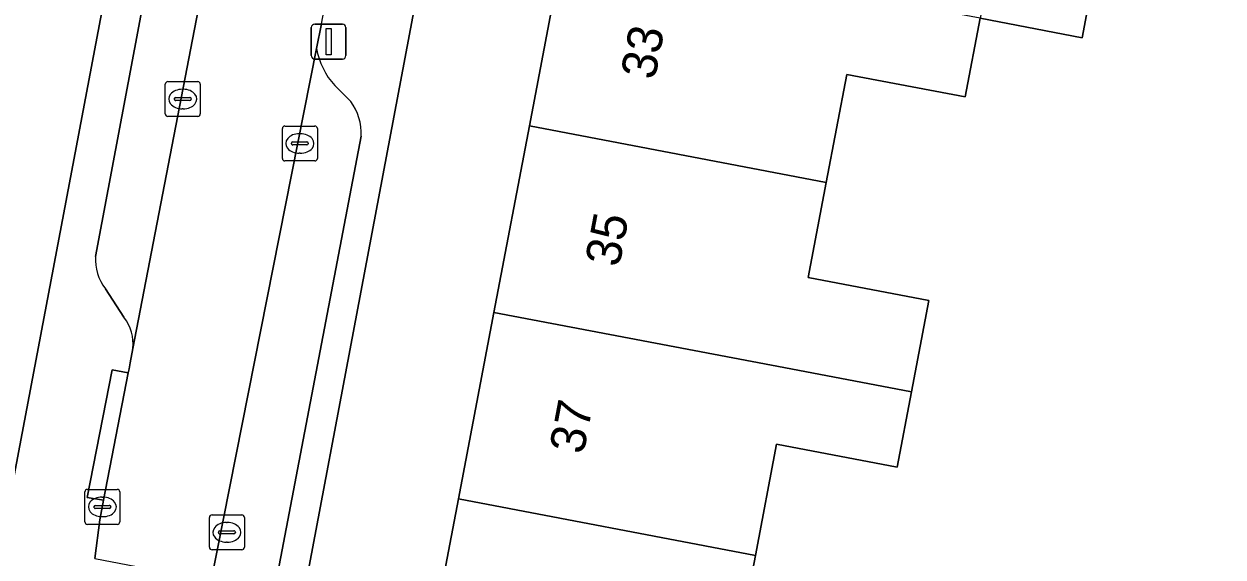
# Model space of a CAD drawing. Extents: x 163147 to 163550, y 380933 to 381639.
# Drawn here: x 163434.83 to 163469.13, y 381049.65 to 381064.9 of the extents above; entities that cross this region are included whole.
import ezdxf

# ---------------------------------------------------------------- set-up
doc = ezdxf.new("R2010")
doc.units = 0
for name, color, linetype in [('IMGEO_Erf', 7, 'Continuous'), ('IMGEO_Kolk', 7, 'Continuous'), ('IMGEO_Lichtmast', 7, 'Continuous'), ('IMGEO_Pand', 7, 'Continuous'), ('IMGEO_Pand_nummerreeks', 7, 'Continuous'), ('IMGEO_Parkeervlak_open', 7, 'Continuous'), ('IMGEO_Rijbaan_lokaal_open', 7, 'Continuous'), ('IMGEO_Voetpad_open', 7, 'Continuous')]:
    doc.layers.add(name, color=color, linetype=linetype)

msp = doc.modelspace()

# ---------------------------------------------------------------- linework, layer by layer
at = {"layer": 'IMGEO_Erf'}
for points in [[(163483.598, 381029.915), (163480.692, 381029.535), (163480.098, 381033.907), (163480.077, 381034.063), (163480.069, 381034.123), (163479.505, 381038.277), (163482.44, 381038.66), (163482.092, 381041.287), (163479.148, 381040.904), (163478.557, 381045.262), (163477.966, 381049.612), (163480.938, 381050), (163480.591, 381052.617), (163477.611, 381052.228), (163477.017, 381056.601), (163476.995, 381056.76), (163476.986, 381056.826), (163476.539, 381060.118), (163479.544, 381060.526), (163479.238, 381062.834), (163475.944, 381087.585), (163462.994, 381085.891), (163449.567, 381084.29), (163437.58, 381020.705)], [(163434.486, 381051.622), (163441.105, 381086.644)], [(163441.133, 381019.158), (163442.172, 381024.615), (163443.189, 381029.953), (163444.206, 381035.291), (163445.223, 381040.63), (163446.239, 381045.968), (163447.256, 381051.307), (163448.273, 381056.645), (163449.29, 381061.984), (163450.306, 381067.322), (163451.323, 381072.66), (163452.34, 381077.999), (163453.379, 381083.454), (163461.861, 381081.838), (163461.562, 381080.269), (163461.308, 381078.937), (163465.15, 381078.205), (163476.21, 381076.097)], [(163476.703, 381073.36), (163464.664, 381075.652), (163464.159, 381073.001), (163460.319, 381073.732), (163459.809, 381071.044), (163459.345, 381068.602), (163463.104, 381067.886), (163463.026, 381067.474), (163465.571, 381066.989), (163465.098, 381064.505), (163462.179, 381065.061), (163461.752, 381062.812), (163458.368, 381063.456), (163457.781, 381060.366), (163457.264, 381057.64), (163460.712, 381056.984), (163460.215, 381054.371), (163459.807, 381052.221), (163456.36, 381052.878), (163455.754, 381049.688), (163455.241, 381046.984)]]:
    msp.add_lwpolyline(points, dxfattribs=at)
at = {"layer": 'IMGEO_Kolk'}
for p, q in [((163438.872, 381062.323), (163438.872, 381063.175)), ((163438.947, 381063.249), (163439.799, 381063.249)), ((163439.36, 381063.029), (163439.385, 381063.029)), ((163439.873, 381063.175), (163439.873, 381062.323)), ((163439.131, 381062.743), (163439.131, 381062.755)), ((163439.569, 381062.706), (163439.171, 381062.706)), ((163439.174, 381062.792), (163439.572, 381062.792)), ((163439.615, 381062.755), (163439.615, 381062.743)), ((163439.383, 381062.469), (163439.358, 381062.469)), ((163439.799, 381062.249), (163438.947, 381062.249)), ((163442.296, 381061.978), (163443.148, 381061.978)), ((163442.221, 381061.052), (163442.221, 381061.904)), ((163442.709, 381061.758), (163442.734, 381061.758)), ((163443.222, 381061.904), (163443.222, 381061.052)), ((163442.48, 381061.472), (163442.48, 381061.484)), ((163442.918, 381061.435), (163442.52, 381061.435)), ((163442.523, 381061.521), (163442.921, 381061.521)), ((163442.964, 381061.484), (163442.964, 381061.472)), ((163443.148, 381060.978), (163442.296, 381060.978)), ((163442.732, 381061.198), (163442.707, 381061.198)), ((163436.572, 381050.655), (163436.572, 381051.507)), ((163436.647, 381051.581), (163437.499, 381051.581)), ((163437.06, 381051.361), (163437.085, 381051.361)), ((163437.573, 381051.507), (163437.573, 381050.655)), ((163436.831, 381051.075), (163436.831, 381051.087)), ((163437.269, 381051.038), (163436.871, 381051.038)), ((163436.874, 381051.124), (163437.272, 381051.124)), ((163437.315, 381051.087), (163437.315, 381051.075)), ((163437.083, 381050.801), (163437.058, 381050.801)), ((163440.134, 381049.927), (163440.134, 381050.779)), ((163440.209, 381050.853), (163441.061, 381050.853)), ((163441.135, 381050.779), (163441.135, 381049.927)), ((163437.499, 381050.581), (163436.647, 381050.581)), ((163440.393, 381050.347), (163440.393, 381050.359)), ((163440.436, 381050.396), (163440.834, 381050.396)), ((163440.622, 381050.633), (163440.647, 381050.633)), ((163440.877, 381050.359), (163440.877, 381050.347)), ((163440.831, 381050.31), (163440.433, 381050.31)), ((163440.645, 381050.073), (163440.62, 381050.073)), ((163441.061, 381049.853), (163440.209, 381049.853))]:
    msp.add_line(p, q, dxfattribs=at)
for points in [[(163438.872, 381062.323), (163438.872, 381063.175)], [(163438.947, 381063.249), (163439.799, 381063.249)], [(163439.873, 381063.175), (163439.873, 381062.323)], [(163439.799, 381062.249), (163438.947, 381062.249)], [(163442.296, 381061.978), (163443.148, 381061.978)], [(163442.221, 381061.052), (163442.221, 381061.904)], [(163443.222, 381061.904), (163443.222, 381061.052)], [(163443.148, 381060.978), (163442.296, 381060.978)], [(163436.572, 381050.655), (163436.572, 381051.507)], [(163436.647, 381051.581), (163437.499, 381051.581)], [(163437.573, 381051.507), (163437.573, 381050.655)], [(163440.134, 381049.927), (163440.134, 381050.779)], [(163440.209, 381050.853), (163441.061, 381050.853)], [(163441.135, 381050.779), (163441.135, 381049.927)], [(163437.499, 381050.581), (163436.647, 381050.581)], [(163441.061, 381049.853), (163440.209, 381049.853)]]:
    msp.add_lwpolyline(points, dxfattribs=at)
for centre, radius, start, end in [((163438.949, 381063.173), 0.0765, 91.552, 178.448), ((163438.949, 381063.173), 0.0765, 91.552, 178.448), ((163439.797, 381063.173), 0.0765, 1.552, 88.448), ((163439.797, 381063.173), 0.0765, 1.552, 88.448), ((163439.171, 381062.752), 0.0403, 85.8775, 175.7526), ((163439.168, 381062.742), 0.0366, 178.938, 274.7102), ((163439.572, 381062.749), 0.043, 264.8664, 352.4533), ((163439.576, 381062.754), 0.0386, 1.7309, 96.639), ((163438.949, 381062.325), 0.0765, 181.552, 268.448), ((163438.949, 381062.325), 0.0765, 181.552, 268.448), ((163439.797, 381062.325), 0.0765, 271.552, 358.448), ((163439.797, 381062.325), 0.0765, 271.552, 358.448), ((163442.298, 381061.902), 0.0765, 91.552, 178.448), ((163442.298, 381061.902), 0.0765, 91.552, 178.448), ((163443.146, 381061.902), 0.0765, 1.552, 88.448), ((163443.146, 381061.902), 0.0765, 1.552, 88.448), ((163442.52, 381061.481), 0.0403, 85.8775, 175.7526), ((163442.517, 381061.471), 0.0366, 178.938, 274.7102), ((163442.921, 381061.478), 0.043, 264.8664, 352.4533), ((163442.925, 381061.483), 0.0386, 1.7309, 96.639), ((163442.298, 381061.054), 0.0765, 181.552, 268.448), ((163442.298, 381061.054), 0.0765, 181.552, 268.448), ((163443.146, 381061.054), 0.0765, 271.552, 358.448), ((163443.146, 381061.054), 0.0765, 271.552, 358.448), ((163436.649, 381051.505), 0.0765, 91.552, 178.448), ((163436.649, 381051.505), 0.0765, 91.552, 178.448), ((163437.497, 381051.505), 0.0765, 1.552, 88.448), ((163437.497, 381051.505), 0.0765, 1.552, 88.448), ((163436.871, 381051.084), 0.0403, 85.8775, 175.7526), ((163436.868, 381051.074), 0.0366, 178.938, 274.7102), ((163437.272, 381051.081), 0.043, 264.8664, 352.4533), ((163437.276, 381051.086), 0.0386, 1.7309, 96.639), ((163436.649, 381050.657), 0.0765, 181.552, 268.448), ((163436.649, 381050.657), 0.0765, 181.552, 268.448), ((163437.497, 381050.657), 0.0765, 271.552, 358.448), ((163437.497, 381050.657), 0.0765, 271.552, 358.448), ((163440.211, 381050.777), 0.0765, 91.552, 178.448), ((163440.211, 381050.777), 0.0765, 91.552, 178.448), ((163441.059, 381050.777), 0.0765, 1.552, 88.448), ((163441.059, 381050.777), 0.0765, 1.552, 88.448), ((163440.433, 381050.356), 0.0403, 85.8775, 175.7526), ((163440.43, 381050.346), 0.0366, 178.938, 274.7102), ((163440.834, 381050.353), 0.043, 264.8664, 352.4533), ((163440.838, 381050.358), 0.0386, 1.7309, 96.639), ((163440.211, 381049.929), 0.0765, 181.552, 268.448), ((163440.211, 381049.929), 0.0765, 181.552, 268.448), ((163441.059, 381049.929), 0.0765, 271.552, 358.448), ((163441.059, 381049.929), 0.0765, 271.552, 358.448)]:
    msp.add_arc(centre, radius, start, end, dxfattribs=at)
for centre, major_axis, ratio, start_param, end_param in [((163439.359, 381062.749), (-0.387, 0.002), 0.722429, 4.712389, 7.853982), ((163439.384, 381062.749), (-0.39, 0.002), 0.717154, 1.570796, 4.712389), ((163442.708, 381061.478), (-0.387, 0.002), 0.722429, 4.712389, 7.853982), ((163442.733, 381061.478), (-0.39, 0.002), 0.717154, 1.570796, 4.712389), ((163437.059, 381051.081), (-0.387, 0.002), 0.722429, 4.712389, 7.853982), ((163437.084, 381051.081), (-0.39, 0.002), 0.717154, 1.570796, 4.712389), ((163440.621, 381050.353), (-0.387, 0.002), 0.722429, 4.712389, 7.853982), ((163440.646, 381050.353), (-0.39, 0.002), 0.717154, 1.570796, 4.712389)]:
    msp.add_ellipse(centre, major_axis=major_axis, ratio=ratio, start_param=start_param, end_param=end_param, dxfattribs=at)
at = {"layer": 'IMGEO_Lichtmast'}
for p, q in [((163443.05, 381063.992), (163443.05, 381064.792)), ((163443.05, 381064.792), (163443.05, 381063.992)), ((163443.15, 381064.892), (163443.94, 381064.892)), ((163443.94, 381064.892), (163443.15, 381064.892)), ((163444.04, 381064.792), (163444.04, 381063.992)), ((163444.04, 381063.992), (163444.04, 381064.792)), ((163443.94, 381063.892), (163443.15, 381063.892)), ((163443.15, 381063.892), (163443.94, 381063.892))]:
    msp.add_line(p, q, dxfattribs=at)
msp.add_lwpolyline([(163443.47, 381064.767), (163443.62, 381064.767), (163443.62, 381064.017), (163443.47, 381064.017), (163443.47, 381064.767)], dxfattribs=at)
for centre, start, end in [((163443.15, 381064.792), 90, 180), ((163443.15, 381064.792), 90, 180), ((163443.94, 381064.792), 0, 90), ((163443.94, 381064.792), 360, 90), ((163443.15, 381063.992), 180, 270), ((163443.15, 381063.992), 180, 270), ((163443.94, 381063.992), 270, 0), ((163443.94, 381063.992), 270, 0)]:
    msp.add_arc(centre, 0.1, start, end, dxfattribs=at)
at = {"layer": 'IMGEO_Pand'}
for points in [[(163463.026, 381067.474), (163462.68, 381065.65), (163462.304, 381065.722), (163462.179, 381065.061), (163465.098, 381064.505), (163465.571, 381066.989)], [(163462.179, 381065.061), (163458.797, 381065.705), (163450.306, 381067.322), (163449.29, 381061.984), (163457.781, 381060.366), (163458.368, 381063.456), (163461.752, 381062.812)], [(163460.215, 381054.371), (163460.712, 381056.984), (163457.264, 381057.64), (163457.781, 381060.366), (163449.29, 381061.984), (163448.273, 381056.645), (163456.769, 381055.027)], [(163460.215, 381054.371), (163456.769, 381055.027), (163448.273, 381056.645), (163447.256, 381051.307), (163455.754, 381049.688), (163456.36, 381052.878), (163459.807, 381052.221)], [(163457.375, 381043.848), (163457.875, 381046.482), (163455.241, 381046.984), (163455.754, 381049.688), (163447.256, 381051.307), (163446.239, 381045.968)]]:
    msp.add_lwpolyline(points, close=True, dxfattribs=at)
at = {"layer": 'IMGEO_Parkeervlak_open'}
for points in [[(163437.946, 381055.613), (163443.442, 381084.114)], [(163441.368, 381082.135), (163436.878, 381058.248)], [(163443.2, 381064.2), (163440.181, 381048.97), (163439.15, 381043.603), (163438.435, 381039.8)], [(163444.176, 381062.683), (163443.726, 381063.134)], [(163440.721, 381042.016), (163444.479, 381061.688)], [(163437.163, 381057.321), (163437.69, 381056.506)]]:
    msp.add_lwpolyline(points, dxfattribs=at)
for centre, radius, start, end in [((163445.228, 381064.538), 2.056, 189.458, 223.0686), ((163442.925, 381061.758), 1.556, 357.4047, 36.4687), ((163438.214, 381058.152), 1.34, 175.8694, 218.31), ((163436.687, 381055.735), 1.265, 354.452, 37.5404)]:
    msp.add_arc(centre, radius, start, end, dxfattribs=at)
at = {"layer": 'IMGEO_Rijbaan_lokaal_open'}
msp.add_lwpolyline([(163443.2, 381064.2), (163443.339, 381064.903), (163446.92, 381083.778), (163443.502, 381084.425), (163443.442, 381084.114), (163437.946, 381055.613), (163437.866, 381055.199), (163437.844, 381055.031), (163437.812, 381054.917), (163437.109, 381051.269), (163437.002, 381050.712), (163436.856, 381049.605), (163440.181, 381048.97)], close=True, dxfattribs=at)
at = {"layer": 'IMGEO_Voetpad_open'}
for points in [[(163412.29, 381000), (163430.255, 381016.703), (163432.143, 381018.005), (163434.736, 381020.337), (163437.58, 381020.705), (163449.567, 381084.29), (163449.459, 381088.154)], [(163441.105, 381086.644), (163434.486, 381051.622), (163433.981, 381048.948), (163433.984, 381048.514), (163432.904, 381040.995)], [(163436.878, 381058.248), (163441.368, 381082.135)], [(163443.339, 381064.903), (163443.2, 381064.2)], [(163443.726, 381063.134), (163444.176, 381062.683)], [(163444.479, 381061.688), (163440.721, 381042.016)], [(163437.69, 381056.506), (163437.163, 381057.321)], [(163436.856, 381049.605), (163437.002, 381050.712), (163437.109, 381051.269), (163436.637, 381051.353), (163437.35, 381055), (163437.812, 381054.917), (163437.844, 381055.031), (163437.866, 381055.199), (163437.946, 381055.613)]]:
    msp.add_lwpolyline(points, dxfattribs=at)
msp.add_lwpolyline([(163437.109, 381051.269), (163437.812, 381054.917), (163437.35, 381055), (163436.637, 381051.353)], close=True, dxfattribs=at)
for centre, radius, start, end in [((163445.228, 381064.538), 2.056, 189.458, 223.0686), ((163442.925, 381061.758), 1.556, 357.4047, 36.4687), ((163438.214, 381058.152), 1.34, 175.8694, 218.31), ((163436.687, 381055.735), 1.265, 354.452, 37.5404)]:
    msp.add_arc(centre, radius, start, end, dxfattribs=at)

# ---------------------------------------------------------------- texts
at = {"layer": 'IMGEO_Pand_nummerreeks'}
for s, p in [('33', (163452.875, 381063.275)), ('35', (163451.855, 381057.917)), ('37', (163450.834, 381052.559))]:
    msp.add_text(s, height=1, rotation=79.2164, dxfattribs=at).set_placement(p)

doc.saveas('drawing.dxf')
